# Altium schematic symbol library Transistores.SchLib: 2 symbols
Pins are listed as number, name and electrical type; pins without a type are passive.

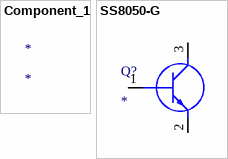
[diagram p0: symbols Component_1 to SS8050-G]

## Component_1
designator *

## SS8050-G
designator Q?
Transistor BJT NPN; Manufacturer_Name: Comchip Technology; Manufacturer_Part_Number: SS8050-G; Description: Bipolar Transistors - BJT NPN TRANSISTOR 1.5A 40V
footprint SOT95P240X115-3N
pins: 1 B, 2 E, 3 C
